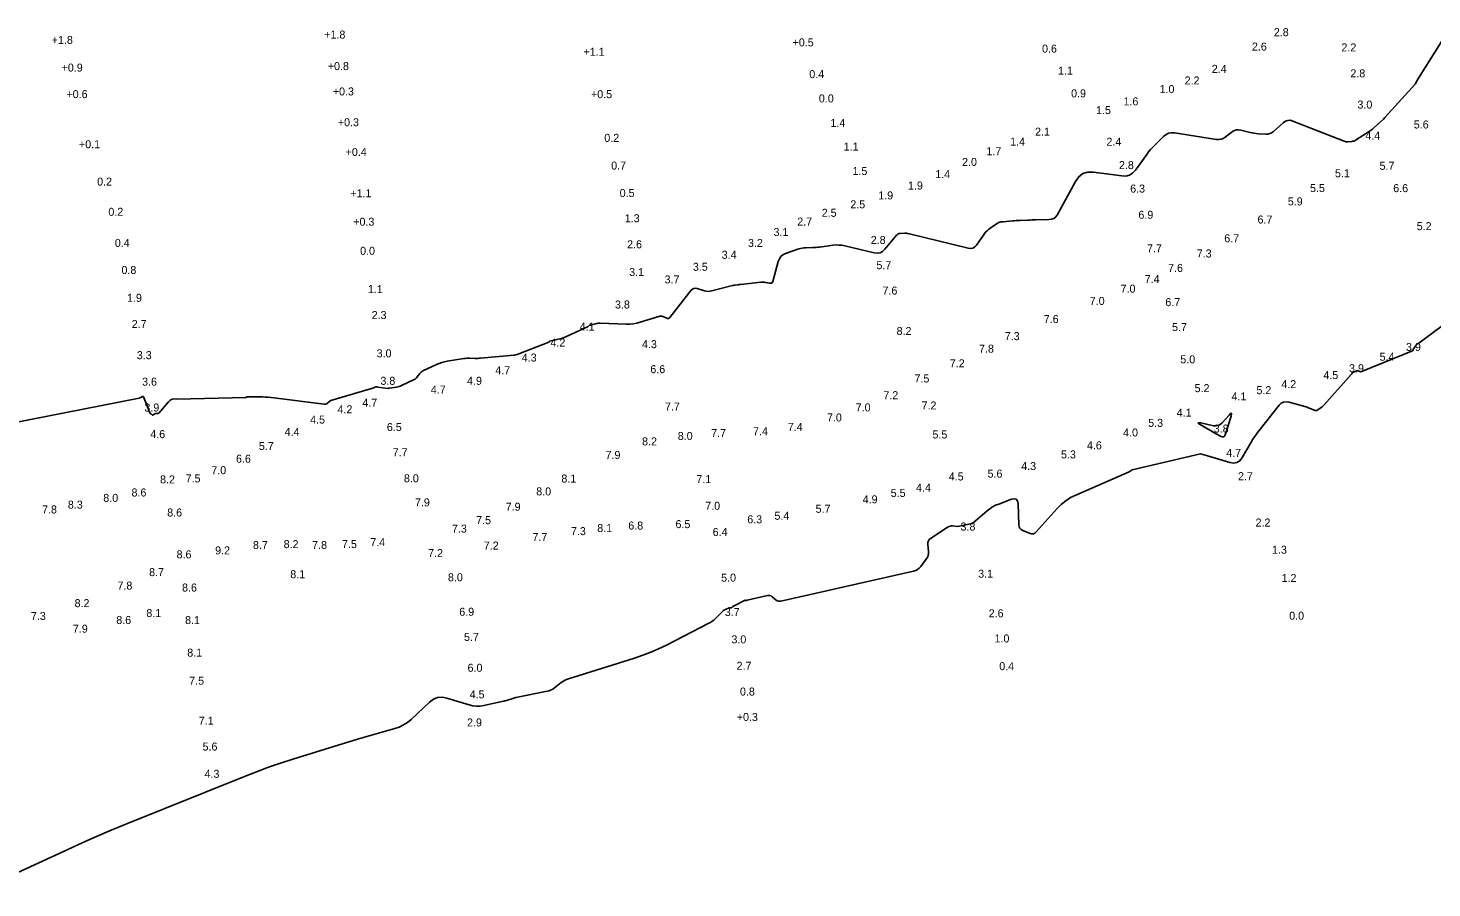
# Model space of a CAD drawing. Extents: x 837127 to 848654, y 3074248 to 3079868.
# Drawn here: x 847285 to 847833, y 3078378 to 3078714 of the extents above; entities that cross this region are included whole.
import ezdxf

# ---------------------------------------------------------------- set-up
doc = ezdxf.new("R2010")
doc.units = 0
for name, color, linetype in [('V-HYDS-MAJR', 7, 'Continuous'), ('V-HYDS-SOUN', 7, 'Continuous'), ('V-HYDS-SOUN-EXSS', 7, 'Continuous')]:
    doc.layers.add(name, color=color, linetype=linetype)

msp = doc.modelspace()

# ---------------------------------------------------------------- linework, layer by layer
at = {"layer": 'V-HYDS-MAJR'}
for points in [[(847837.52, 3078710.38), (847827.04, 3078693.68), (847826.49, 3078692.47), (847814.5, 3078679.27), (847813.96, 3078678.68), (847810.37, 3078675.44), (847809.64, 3078674.81), (847808.89, 3078674.22), (847808.11, 3078673.65), (847807.31, 3078673.12), (847803.08, 3078670.42), (847802.75, 3078670.24), (847802.4, 3078670.1), (847802.03, 3078670), (847801.65, 3078669.94), (847800.11, 3078669.81), (847799.73, 3078669.8), (847799.35, 3078669.83), (847798.98, 3078669.9), (847798.62, 3078670.02), (847778.61, 3078677.93), (847777.57, 3078678.2), (847776.59, 3078678.18), (847775.66, 3078677.86), (847774.78, 3078677.25), (847770.83, 3078673.75), (847770.22, 3078673.3), (847769.57, 3078672.99), (847768.86, 3078672.82), (847768.1, 3078672.8), (847764.99, 3078672.98), (847764.21, 3078673.04), (847763.44, 3078673.14), (847762.67, 3078673.28), (847761.91, 3078673.46), (847758.23, 3078674.4), (847757.38, 3078674.52), (847756.57, 3078674.46), (847755.8, 3078674.21), (847755.06, 3078673.77), (847752.09, 3078671.57), (847751.34, 3078671.11), (847750.54, 3078670.82), (847749.7, 3078670.7), (847748.82, 3078670.76), (847732.31, 3078673.3), (847731.15, 3078673.35), (847730.07, 3078673.15), (847729.07, 3078672.68), (847728.16, 3078671.96), (847724.69, 3078668.54), (847723.84, 3078667.67), (847723.03, 3078666.77), (847722.26, 3078665.83), (847721.53, 3078664.86), (847717.07, 3078658.72), (847716.01, 3078657.56), (847714.77, 3078656.8), (847713.37, 3078656.43), (847711.8, 3078656.46), (847700.76, 3078657.95), (847698.53, 3078657.96), (847696.6, 3078657.37), (847694.98, 3078656.17), (847693.67, 3078654.36), (847686.61, 3078641.39), (847686, 3078640.53), (847685.25, 3078639.91), (847684.35, 3078639.53), (847683.31, 3078639.39), (847678.12, 3078639.3), (847677.36, 3078639.29), (847676.61, 3078639.27), (847675.85, 3078639.24), (847675.1, 3078639.21), (847672.08, 3078639.08), (847671.32, 3078639.05), (847670.57, 3078639.01), (847669.81, 3078638.96), (847669.06, 3078638.9), (847665.29, 3078638.6), (847664.52, 3078638.48), (847663.79, 3078638.27), (847663.09, 3078637.95), (847662.44, 3078637.53), (847659.89, 3078635.64), (847659.28, 3078635.15), (847658.71, 3078634.61), (847658.19, 3078634.02), (847657.71, 3078633.39), (847655.01, 3078629.46), (847654.36, 3078628.73), (847653.6, 3078628.28), (847652.73, 3078628.11), (847651.75, 3078628.23), (847628.82, 3078633.89), (847628.38, 3078633.98), (847627.94, 3078634.04), (847627.5, 3078634.07), (847627.06, 3078634.07), (847625.28, 3078634), (847624.86, 3078633.94), (847624.47, 3078633.8), (847624.12, 3078633.58), (847623.82, 3078633.28), (847619.28, 3078627.86), (847618.38, 3078627), (847617.36, 3078626.48), (847616.23, 3078626.29), (847615, 3078626.44), (847603.54, 3078629.17), (847602.44, 3078629.38), (847601.33, 3078629.49), (847600.22, 3078629.5), (847599.11, 3078629.4), (847593.75, 3078628.69), (847593.07, 3078628.61), (847592.39, 3078628.55), (847591.71, 3078628.51), (847591.03, 3078628.49), (847588.31, 3078628.45), (847587.64, 3078628.41), (847586.97, 3078628.32), (847586.32, 3078628.17), (847585.67, 3078627.97), (847580.42, 3078626.11), (847579.43, 3078625.63), (847578.63, 3078624.97), (847578.03, 3078624.13), (847577.62, 3078623.11), (847575.43, 3078615.23), (847575.27, 3078614.87), (847575.03, 3078614.63), (847574.71, 3078614.52), (847574.31, 3078614.53), (847572.54, 3078614.87), (847572.1, 3078614.93), (847571.66, 3078614.97), (847571.21, 3078614.97), (847570.77, 3078614.94), (847562.82, 3078614.07), (847562.56, 3078614.04), (847562.31, 3078614.01), (847562.05, 3078613.98), (847561.8, 3078613.95), (847560.78, 3078613.82), (847560.52, 3078613.79), (847560.27, 3078613.74), (847560.02, 3078613.69), (847559.77, 3078613.63), (847551.66, 3078611.55), (847550.94, 3078611.42), (847550.22, 3078611.39), (847549.51, 3078611.46), (847548.8, 3078611.63), (847545.95, 3078612.52), (847545.27, 3078612.64), (847544.65, 3078612.56), (847544.1, 3078612.28), (847543.61, 3078611.79), (847535.29, 3078601.18), (847535.02, 3078600.91), (847534.72, 3078600.77), (847534.38, 3078600.75), (847534.02, 3078600.85), (847532.49, 3078601.51), (847532.1, 3078601.64), (847531.72, 3078601.69), (847531.33, 3078601.68), (847530.93, 3078601.59), (847523.68, 3078599.32), (847522.33, 3078598.96), (847520.96, 3078598.72), (847519.58, 3078598.59), (847518.19, 3078598.58), (847508.09, 3078598.92), (847507.73, 3078598.92), (847507.38, 3078598.89), (847507.03, 3078598.84), (847506.68, 3078598.76), (847504.77, 3078598.25), (847504.69, 3078598.23), (847504.6, 3078598.22), (847504.52, 3078598.21), (847504.44, 3078598.21), (847504.1, 3078598.22), (847504.01, 3078598.21), (847503.94, 3078598.19), (847503.87, 3078598.15), (847503.81, 3078598.1), (847503.46, 3078597.75), (847503.38, 3078597.67), (847503.3, 3078597.61), (847503.21, 3078597.55), (847503.11, 3078597.5), (847493.69, 3078593.24), (847493.63, 3078593.21), (847493.56, 3078593.18), (847493.49, 3078593.16), (847493.43, 3078593.13), (847493.16, 3078593.04), (847493.09, 3078593.01), (847493.02, 3078592.99), (847492.95, 3078592.97), (847492.88, 3078592.96), (847488.35, 3078591.95), (847488.3, 3078591.93), (847488.25, 3078591.91), (847488.22, 3078591.87), (847488.19, 3078591.83), (847488.09, 3078591.63), (847488.07, 3078591.59), (847488.03, 3078591.55), (847487.99, 3078591.52), (847487.94, 3078591.5), (847476.31, 3078586.98), (847476.15, 3078586.92), (847475.99, 3078586.87), (847475.83, 3078586.81), (847475.67, 3078586.76), (847475.02, 3078586.56), (847474.86, 3078586.51), (847474.69, 3078586.48), (847474.53, 3078586.45), (847474.36, 3078586.43), (847461.37, 3078585.26), (847460.83, 3078585.22), (847460.28, 3078585.19), (847459.74, 3078585.18), (847459.2, 3078585.19), (847457.02, 3078585.25), (847456.48, 3078585.25), (847455.94, 3078585.23), (847455.4, 3078585.19), (847454.86, 3078585.12), (847448.29, 3078584.1), (847447.21, 3078583.89), (847446.15, 3078583.61), (847445.11, 3078583.25), (847444.1, 3078582.81), (847438.85, 3078580.3), (847438.49, 3078580.1), (847438.16, 3078579.86), (847437.87, 3078579.59), (847437.61, 3078579.28), (847436.62, 3078577.95), (847436.35, 3078577.63), (847436.06, 3078577.36), (847435.73, 3078577.12), (847435.38, 3078576.92), (847430.49, 3078574.57), (847430, 3078574.36), (847429.51, 3078574.19), (847429, 3078574.06), (847428.49, 3078573.97), (847425.8, 3078573.6), (847425.58, 3078573.56), (847425.35, 3078573.51), (847425.13, 3078573.46), (847421.19, 3078573.93), (847420.8, 3078574.04), (847420.42, 3078574.05), (847420.05, 3078573.95), (847419.7, 3078573.75), (847402.92, 3078568.75), (847402.64, 3078568.56), (847401.54, 3078567.67), (847401.26, 3078567.48), (847400.96, 3078567.36), (847400.64, 3078567.31), (847400.3, 3078567.32), (847380.57, 3078569.82), (847379.47, 3078569.95), (847378.36, 3078570.04), (847377.26, 3078570.1), (847376.16, 3078570.13), (847370.82, 3078570.2), (847370.2, 3078570.14), (847369.67, 3078569.93), (847342.72, 3078569.23), (847341.78, 3078569.36), (847340.91, 3078569.23), (847340.13, 3078568.85), (847339.43, 3078568.21), (847335.64, 3078563.82), (847335.54, 3078563.73), (847335.43, 3078563.67), (847335.3, 3078563.63), (847335.16, 3078563.63), (847334.58, 3078563.68), (847334.44, 3078563.67), (847334.31, 3078563.65), (847334.18, 3078563.6), (847334.06, 3078563.52), (847333.49, 3078563.1), (847333.39, 3078563.04), (847333.3, 3078563.03), (847333.21, 3078563.05), (847333.12, 3078563.11), (847332.63, 3078563.53), (847332.6, 3078563.55), (847332.57, 3078563.57), (847332.54, 3078563.58), (847332.51, 3078563.58), (847332.36, 3078563.58), (847332.33, 3078563.58), (847332.3, 3078563.59), (847332.28, 3078563.62), (847332.26, 3078563.64), (847329.73, 3078570.11), (847329.66, 3078570.25), (847329.56, 3078570.32), (847329.43, 3078570.33), (847329.29, 3078570.28), (847328.66, 3078569.94), (847328.51, 3078569.87), (847328.34, 3078569.8), (847328.17, 3078569.75), (847328, 3078569.71), (847255.65, 3078555.5)], [(847267.44, 3078378.32), (847300.09, 3078393.35), (847305.73, 3078395.91), (847311.4, 3078398.4), (847317.1, 3078400.82), (847322.82, 3078403.17), (847369.09, 3078421.87), (847373.78, 3078423.7), (847378.5, 3078425.44), (847383.26, 3078427.08), (847388.05, 3078428.62), (847413.3, 3078436.44), (847415.1, 3078436.99), (847416.91, 3078437.53), (847418.73, 3078438.05), (847420.55, 3078438.57), (847427.83, 3078440.58), (847429.59, 3078441.18), (847431.25, 3078441.98), (847432.79, 3078442.98), (847434.22, 3078444.17), (847441.39, 3078450.9), (847442.91, 3078452.03), (847444.55, 3078452.67), (847446.3, 3078452.82), (847448.17, 3078452.47), (847456.9, 3078449.8), (847458.3, 3078449.46), (847459.71, 3078449.31), (847461.13, 3078449.35), (847462.56, 3078449.57), (847470.32, 3078451.27), (847470.72, 3078451.37), (847471.12, 3078451.47), (847471.52, 3078451.59), (847471.92, 3078451.72), (847473.5, 3078452.25), (847473.89, 3078452.38), (847474.29, 3078452.49), (847474.69, 3078452.6), (847475.1, 3078452.68), (847487.37, 3078455.15), (847488.15, 3078455.36), (847488.9, 3078455.65), (847489.6, 3078456.02), (847490.26, 3078456.49), (847492.81, 3078458.52), (847493.47, 3078458.99), (847494.16, 3078459.4), (847494.89, 3078459.75), (847495.65, 3078460.02), (847521.46, 3078468.14), (847524.65, 3078469.21), (847527.78, 3078470.42), (847530.87, 3078471.75), (847533.89, 3078473.22), (847550.53, 3078481.69), (847551.2, 3078482.06), (847551.83, 3078482.49), (847552.43, 3078482.96), (847552.99, 3078483.48), (847556.04, 3078486.59), (847556.12, 3078486.69), (847558.48, 3078487.68), (847558.88, 3078487.7), (847559.26, 3078487.79), (847559.6, 3078487.96), (847559.92, 3078488.21), (847564.73, 3078490.68), (847564.96, 3078490.66), (847565.2, 3078490.66), (847565.45, 3078490.7), (847573.4, 3078492.52), (847573.9, 3078492.58), (847574.37, 3078492.53), (847574.81, 3078492.37), (847575.22, 3078492.1), (847576.83, 3078490.78), (847577.24, 3078490.51), (847577.69, 3078490.34), (847578.15, 3078490.29), (847578.65, 3078490.35), (847630.44, 3078502.09), (847631.27, 3078502.36), (847632.02, 3078502.75), (847632.68, 3078503.28), (847633.25, 3078503.94), (847635.59, 3078507.13), (847635.96, 3078507.73), (847636.2, 3078508.37), (847636.32, 3078509.03), (847636.31, 3078509.74), (847636.05, 3078512.61), (847636.06, 3078513.29), (847636.25, 3078513.88), (847636.6, 3078514.4), (847637.12, 3078514.84), (847643.99, 3078519.35), (847644.4, 3078519.57), (847644.82, 3078519.71), (847645.26, 3078519.78), (847645.72, 3078519.77), (847647.59, 3078519.57), (847653.3, 3078520.66), (847653.68, 3078520.9), (847659.2, 3078525.66), (847660.24, 3078526.47), (847661.33, 3078527.18), (847662.48, 3078527.79), (847663.7, 3078528.3), (847668.67, 3078530.14), (847669.76, 3078530.38), (847670.56, 3078530.17), (847671.06, 3078529.51), (847671.26, 3078528.41), (847671.61, 3078520.12), (847671.73, 3078519.41), (847672.01, 3078518.82), (847672.47, 3078518.35), (847673.1, 3078517.99), (847675.94, 3078516.82), (847676.63, 3078516.63), (847677.26, 3078516.66), (847677.85, 3078516.91), (847678.39, 3078517.38), (847686.52, 3078526.54), (847688.12, 3078528.16), (847689.87, 3078529.58), (847691.76, 3078530.79), (847693.8, 3078531.81), (847714.62, 3078540.85), (847715.87, 3078541.6), (847742.53, 3078547.97), (847744.36, 3078547.45), (847746.18, 3078546.91), (847753.91, 3078544.52), (847755.41, 3078544.27), (847756.72, 3078544.5), (847757.85, 3078545.22), (847758.78, 3078546.42), (847762.15, 3078552.2), (847763.01, 3078553.63), (847763.93, 3078555.02), (847764.9, 3078556.38), (847765.91, 3078557.7), (847773.23, 3078566.86), (847774.04, 3078567.66), (847774.96, 3078568.13), (847775.98, 3078568.28), (847777.11, 3078568.11), (847783.26, 3078566.39), (847783.72, 3078566.25), (847784.17, 3078566.1), (847784.62, 3078565.93), (847785.06, 3078565.74), (847786.95, 3078564.91), (847787.32, 3078564.79), (847787.67, 3078564.78), (847788.01, 3078564.86), (847788.34, 3078565.05), (847789.66, 3078565.98), (847789.98, 3078566.22), (847790.28, 3078566.48), (847790.57, 3078566.75), (847790.85, 3078567.04), (847801.38, 3078578.87), (847801.57, 3078579.12), (847801.72, 3078579.39), (847801.83, 3078579.68), (847804.04, 3078580.51), (847804.36, 3078580.25), (847804.73, 3078580.07), (847805.15, 3078579.97), (847825.31, 3078588.19), (847825.45, 3078588.5), (847826.29, 3078589.82), (847826.52, 3078590.13), (847826.76, 3078590.42), (847827.04, 3078590.69), (847827.34, 3078590.93), (847839.42, 3078599.71)]]:
    msp.add_lwpolyline(points, dxfattribs=at)
msp.add_lwpolyline([(847751.53, 3078554.56), (847751.1, 3078554.52), (847750.59, 3078554.7), (847748.34, 3078555.91), (847747.78, 3078556.21), (847747.22, 3078556.52), (847746.67, 3078556.84), (847746.12, 3078557.16), (847742.38, 3078559.39), (847741.79, 3078559.79), (847741.63, 3078560.02), (847741.9, 3078560.07), (847742.6, 3078559.96), (847747.55, 3078558.9), (847748.51, 3078558.81), (847749.4, 3078558.96), (847750.21, 3078559.36), (847750.93, 3078560), (847753.68, 3078563.07), (847754.24, 3078563.62), (847754.55, 3078563.74), (847754.61, 3078563.41), (847754.43, 3078562.65), (847752.1, 3078555.32), (847751.86, 3078554.82)], close=True, dxfattribs=at)

# ---------------------------------------------------------------- texts
at = {"layer": 'V-HYDS-SOUN'}
for s, p in [('+1.8 ', (847293.86, 3078708.05)), ('+1.8 ', (847400.28, 3078710.14)), ('+0.5 ', (847583.19, 3078707.09)), ('2.8', (847771.15, 3078711.07)), ('+1.1 ', (847501.54, 3078703.43)), ('0.6', (847680.63, 3078704.65)), ('2.6', (847762.59, 3078705.44)), ('2.2', (847797.55, 3078705.12)), ('+0.9 ', (847297.69, 3078697.24)), ('+0.8 ', (847401.67, 3078697.82)), ('1.1', (847686.84, 3078696.03)), ('2.4', (847746.92, 3078696.74)), ('0.4', (847589.73, 3078694.69)), ('2.2', (847736.31, 3078692.21)), ('2.8', (847801.05, 3078694.99)), ('+0.6 ', (847299.6, 3078686.87)), ('+0.3 ', (847403.63, 3078687.92)), ('+0.5 ', (847504.46, 3078686.86)), (' 0.0', (847592.3, 3078685.19)), ('0.9', (847691.97, 3078687.17)), ('1.0', (847726.52, 3078688.83)), ('1.5', (847701.73, 3078680.63)), ('1.6', (847712.44, 3078684.04)), ('3.0', (847803.81, 3078682.78)), ('+0.3 ', (847405.59, 3078675.88)), ('1.4', (847597.97, 3078675.62)), ('5.6', (847825.81, 3078675.02)), ('0.2', (847509.67, 3078669.79)), ('1.4', (847668.18, 3078668.34)), ('2.1', (847677.89, 3078672.2)), ('2.4', (847705.78, 3078668.27)), ('4.4', (847806.89, 3078670.7)), ('+0.1 ', (847304.49, 3078667.3)), ('+0.4 ', (847408.64, 3078664.29)), ('1.1', (847603.14, 3078666.34)), ('1.7', (847658.91, 3078664.57)), ('0.7', (847512.36, 3078658.97)), ('2.0', (847649.39, 3078660.38)), ('2.8', (847710.67, 3078659.16)), ('5.7', (847812.44, 3078658.86)), ('0.2', (847311.59, 3078652.69)), ('1.5', (847606.59, 3078656.83)), ('1.4', (847638.91, 3078655.61)), ('5.1', (847795.05, 3078655.96)), ('+1.1 ', (847410.46, 3078648.15)), ('0.5', (847515.67, 3078648.24)), ('1.9', (847616.67, 3078647.31)), ('1.9', (847628.27, 3078651.16)), ('6.3', (847715.05, 3078649.97)), ('5.5', (847785.29, 3078650.18)), ('6.6', (847817.79, 3078650.14)), ('0.2', (847315.97, 3078640.91)), ('2.5', (847605.75, 3078643.82)), ('5.9', (847776.61, 3078644.96)), ('+0.3 ', (847411.6, 3078637.02)), ('1.3', (847517.66, 3078638.38)), ('2.7', (847585.01, 3078637.08)), ('2.5', (847594.58, 3078640.52)), ('6.9', (847718.26, 3078639.73)), ('6.7', (847764.79, 3078637.88)), ('3.1', (847575.75, 3078633)), ('2.8', (847613.73, 3078629.9)), ('6.7', (847751.79, 3078630.55)), ('5.2', (847826.96, 3078635.29)), ('0.4', (847318.49, 3078628.75)), (' 0.0', (847413.13, 3078625.67)), ('2.6', (847518.57, 3078628.21)), ('3.2', (847565.77, 3078628.72)), ('7.7', (847721.63, 3078626.63)), ('7.3', (847741.05, 3078624.62)), ('3.5', (847544.26, 3078619.42)), ('3.4', (847555.5, 3078624.1)), ('5.7', (847615.94, 3078620.04)), ('7.6', (847729.85, 3078618.97)), ('0.8', (847321.08, 3078618.17)), ('3.1', (847519.39, 3078617.38)), ('3.7', (847533.2, 3078614.48)), ('7.4', (847720.73, 3078614.64)), ('1.1', (847417.32, 3078610.72)), ('7.6', (847618.31, 3078610.12)), ('7.0', (847711.3, 3078610.87)), ('1.9', (847323.26, 3078607.3)), ('3.8', (847513.84, 3078604.68)), ('7.0', (847699.26, 3078606.08)), ('6.7', (847728.78, 3078605.61)), ('2.7', (847325.1, 3078597.07)), ('2.3', (847418.8, 3078600.56)), ('7.6', (847681.29, 3078599.03)), ('4.1', (847500.04, 3078596.08)), ('8.2', (847623.83, 3078594.33)), ('7.3', (847666.07, 3078592.32)), ('5.7', (847731.4, 3078595.86)), ('4.2', (847488.64, 3078589.83)), ('4.3', (847524.39, 3078589.19)), ('7.8', (847656.02, 3078587.43)), ('3.9', (847822.78, 3078588.1)), ('3.3', (847327.08, 3078584.89)), ('3.0', (847420.74, 3078585.61)), ('4.3', (847477.43, 3078583.95)), ('7.2', (847644.6, 3078581.71)), ('5.0', (847734.64, 3078583.28)), ('5.4', (847812.45, 3078584.28)), ('6.6', (847527.64, 3078579.41)), ('7.5', (847630.81, 3078575.79)), ('4.5', (847790.5, 3078577.1)), ('3.9', (847800.53, 3078579.8)), ('3.6', (847329.14, 3078574.53)), ('3.8', (847422.22, 3078574.87)), ('4.7', (847441.91, 3078571.45)), ('4.9', (847456.06, 3078574.87)), ('5.2', (847740.22, 3078572)), ('5.2', (847764.37, 3078571.22)), ('4.2', (847774.09, 3078573.57)), ('3.9', (847330.03, 3078564.44)), ('4.7', (847415.17, 3078566.31)), ('7.7', (847533.34, 3078564.8)), ('7.0', (847607.86, 3078564.49)), ('7.2', (847618.66, 3078569.25)), ('7.2', (847633.58, 3078565.24)), ('4.1', (847754.63, 3078568.81)), ('4.5', (847394.78, 3078559.73)), ('4.2', (847405.45, 3078563.76)), ('7.0', (847596.63, 3078560.55)), ('4.1', (847733.21, 3078562.43)), ('4.6', (847332.34, 3078554.03)), ('4.4', (847384.8, 3078554.9)), ('6.5', (847424.74, 3078556.81)), ('8.0', (847538.36, 3078553.33)), ('7.7', (847551.4, 3078554.46)), ('7.4', (847567.75, 3078555.16)), ('7.4', (847581.35, 3078556.86)), ('5.5', (847637.83, 3078553.91)), ('4.0', (847712.29, 3078554.69)), ('5.3', (847722.08, 3078558.45)), ('3.8', (847747.69, 3078556.21)), ('5.7', (847374.74, 3078549.4)), ('8.2', (847524.42, 3078551.2)), ('4.6', (847698.16, 3078549.66)), ('6.6', (847365.82, 3078544.43)), ('7.7', (847427.01, 3078546.96)), ('7.9', (847510.15, 3078545.91)), ('5.3', (847688.03, 3078546.11)), ('4.7', (847752.57, 3078546.72)), ('7.5', (847346.16, 3078536.74)), ('7.0', (847356.18, 3078539.96)), ('8.0', (847431.4, 3078536.79)), ('8.1', (847492.89, 3078536.7)), ('4.5', (847644.2, 3078537.51)), ('5.6', (847659.34, 3078538.6)), ('4.3', (847672.5, 3078541.57)), ('2.7', (847757.15, 3078537.61)), ('8.6', (847325.01, 3078531.24)), ('8.2', (847336.17, 3078536.36)), ('7.1', (847545.6, 3078536.47)), ('4.4', (847631.43, 3078533.14)), ('8.3', (847300.15, 3078526.5)), ('8.0', (847313.99, 3078529.14)), ('7.9', (847435.71, 3078527.38)), ('7.0', (847549.09, 3078526.05)), ('4.9', (847610.57, 3078528.57)), ('5.5', (847621.52, 3078531.07)), ('7.8', (847290.08, 3078524.61)), ('8.6', (847338.95, 3078523.42)), ('7.5', (847459.61, 3078520.43)), ('7.9', (847471.15, 3078525.68)), ('6.3', (847565.5, 3078520.76)), ('5.4', (847576.11, 3078522.14)), ('5.7', (847592.19, 3078524.88)), ('7.3', (847450.17, 3078517.12)), ('7.3', (847496.64, 3078516.15)), ('8.1', (847506.91, 3078517.35)), ('6.8', (847519.04, 3078518.32)), ('6.5', (847537.46, 3078518.88)), ('6.4', (847551.99, 3078515.82)), ('3.8', (847648.79, 3078517.93)), ('2.2', (847764.03, 3078519.51)), ('8.7', (847372.45, 3078510.72)), ('8.2', (847384.43, 3078511.07)), ('7.8', (847395.56, 3078510.74)), ('7.5', (847407.22, 3078511.09)), ('7.4', (847418.26, 3078511.84)), ('7.2', (847462.6, 3078510.51)), ('7.7', (847481.6, 3078513.83)), ('8.6', (847342.61, 3078507.06)), ('9.2', (847357.68, 3078508.62)), ('7.2', (847440.85, 3078507.58)), ('1.3', (847770.43, 3078508.89)), ('8.7', (847331.88, 3078500.13)), ('8.1', (847387.02, 3078499.31)), ('3.1', (847655.69, 3078499.52)), ('7.8', (847319.52, 3078494.87)), ('8.6', (847344.75, 3078494.11)), ('8.0', (847448.59, 3078498.12)), ('5.0', (847555.29, 3078497.97)), ('1.2', (847774.18, 3078497.84)), ('8.2', (847302.78, 3078488.01)), ('7.3', (847285.72, 3078482.99)), ('8.1', (847330.8, 3078484.13)), ('6.9', (847453.02, 3078484.65)), ('3.7', (847556.71, 3078484.54)), ('2.6', (847659.79, 3078484.05)), (' 0.0', (847775.99, 3078483.1)), ('7.9', (847302.11, 3078478.03)), ('8.6', (847319.06, 3078481.43)), ('8.1', (847345.93, 3078481.4)), ('5.7', (847454.87, 3078474.81)), ('3.0', (847559.31, 3078473.86)), ('1.0', (847662.07, 3078474.22)), ('8.1', (847346.78, 3078468.66)), ('6.0', (847456.26, 3078462.76)), ('2.7', (847561.33, 3078463.54)), ('0.4', (847663.92, 3078463.39)), ('7.5', (847347.53, 3078457.71)), ('4.5', (847457.07, 3078452.37)), ('0.8', (847562.64, 3078453.48)), ('+0.3 ', (847561.4, 3078443.53)), ('7.1', (847351.28, 3078442.11)), ('2.9', (847456.05, 3078441.4)), ('5.6', (847352.76, 3078431.97)), ('4.3', (847353.53, 3078421.34))]:
    msp.add_text(s, height=3.125, dxfattribs=at).set_placement(p)
at = {"layer": 'V-HYDS-SOUN-EXSS'}
for s, p in [('4.7', (847467.09, 3078578.99)), ('8.0', (847483.08, 3078531.66))]:
    msp.add_text(s, height=3.125, dxfattribs=at).set_placement(p)

doc.saveas('drawing.dxf')
